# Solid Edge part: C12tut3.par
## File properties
Author: CADCIM
Template: ansi part.par
Last saved by: Ashutosh-CADCIM
Revision: 11
Application: Solid Edge
Accuracy: 0.990
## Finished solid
Body 1: solid body, 13 faces, 19 edges, 8 vertices.
  Faces by surface: plane 9, cylinder 4
  Edges by curve: line 10, circle 8, ellipse 1
Bounding box of the edges (mm): 31.750 x 82.544 x 31.750, from (-15.875, -77.8163, -15.875) to (15.875, 4.7283, 15.875).
Cylindrical faces by radius (mm): R5.5944 x1, R6.35 x1, R7.9375 x1, R15.875 x1
Planar faces by outward normal: +x 1, +y 1, +z 1, -x 1, -y 4, oblique 1
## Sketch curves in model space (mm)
line (-22.2359, -0.0325, 12.7) -> (-22.2334, -4.7925, 7.935)
line (-22.2322, -77.8163, 5.5531) -> (-22.2323, -0.0289, 5.77)
line (-22.2262, -77.8103, -5.6356) -> (-22.2263, -0.0229, -5.5751)
line (-22.2326, -68.2917, 6.3138) -> (-22.2326, -77.8167, 6.3087)
line (-22.2326, -77.8167, 6.3087) -> (-22.2258, -77.8099, -6.3913)
line (-22.2258, -68.2849, -6.3862) -> (-22.2258, -77.8099, -6.3913)
line (-22.2376, -0.0342, 15.875) -> (-22.2208, -0.0174, -15.875)
line (-22.2376, 4.7283, 15.8775) -> (-22.2376, -0.0342, 15.875)
line (-22.2376, 4.7283, 15.8775) -> (-22.2208, 4.7451, -15.8725)
line (-22.2208, 4.7451, -15.8725) -> (-22.2208, -0.0174, -15.875)
line (-22.225, -0.0216, -7.9375) -> (-22.225, -68.2841, -7.9737)
line (-22.2334, -0.03, 7.9375) -> (-22.2334, -68.2925, 7.9013)
line (-22.2334, -68.2925, 7.9013) -> (-22.225, -68.2841, -7.9737)
line (0, 0, 22.225) -> (0, 0, -22.225)
line (22.225, 0, 0) -> (-22.225, 0, 0)
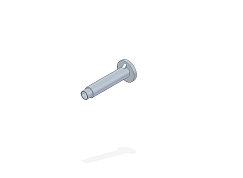
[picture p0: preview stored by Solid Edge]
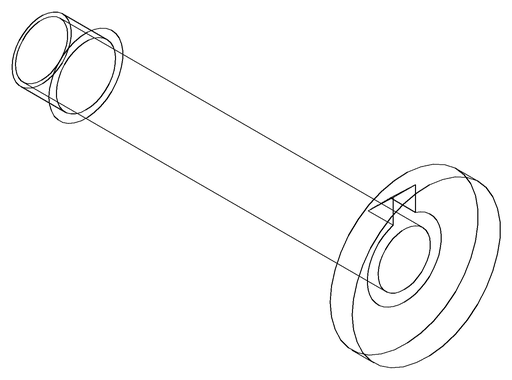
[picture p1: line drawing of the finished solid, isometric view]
